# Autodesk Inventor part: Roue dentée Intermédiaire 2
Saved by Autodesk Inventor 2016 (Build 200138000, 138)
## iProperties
Created: 2013-08
Part Number: Roue dentée Intermédiaire 2
Material: Générique
Document SubType Name: Modeling
Designer: hilarion
Density: 1 g/cm^3
Appearance: Par défaut
Author: Balduini Gael & Faure Olivier
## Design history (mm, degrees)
node "Roue dentée Intermédiaire 21"
node "Roue dentée Intermédiaire 2"
node "Base1"
